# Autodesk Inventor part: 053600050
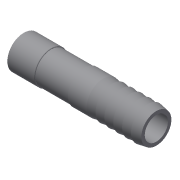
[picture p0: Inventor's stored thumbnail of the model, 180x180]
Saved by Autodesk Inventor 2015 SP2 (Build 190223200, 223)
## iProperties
Created: 2017-10
Part Number: 053600050
Material: Generic
Description: PLASSON HOSE NOZZLE-CEM. PVC 50
Document SubType Name: Modeling
Designer: KIM
Density: 1 g/cm^3
Appearance: Default
Author: KIM
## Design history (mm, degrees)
derived "053600.ipt"
feature "Solid1::053600.ipt"
tag "TaggingFeature1"
body "Solid1"
other parameters: "d0" = 102, "d1" = 170 deg, "d4" = 31, "d6" = 35, "d8" = 40.8, "d9" = 48, "d10" = 25.5, "d11" = 0.5, "d14" = 0.5, "H_" = 102, "L_" = 31
